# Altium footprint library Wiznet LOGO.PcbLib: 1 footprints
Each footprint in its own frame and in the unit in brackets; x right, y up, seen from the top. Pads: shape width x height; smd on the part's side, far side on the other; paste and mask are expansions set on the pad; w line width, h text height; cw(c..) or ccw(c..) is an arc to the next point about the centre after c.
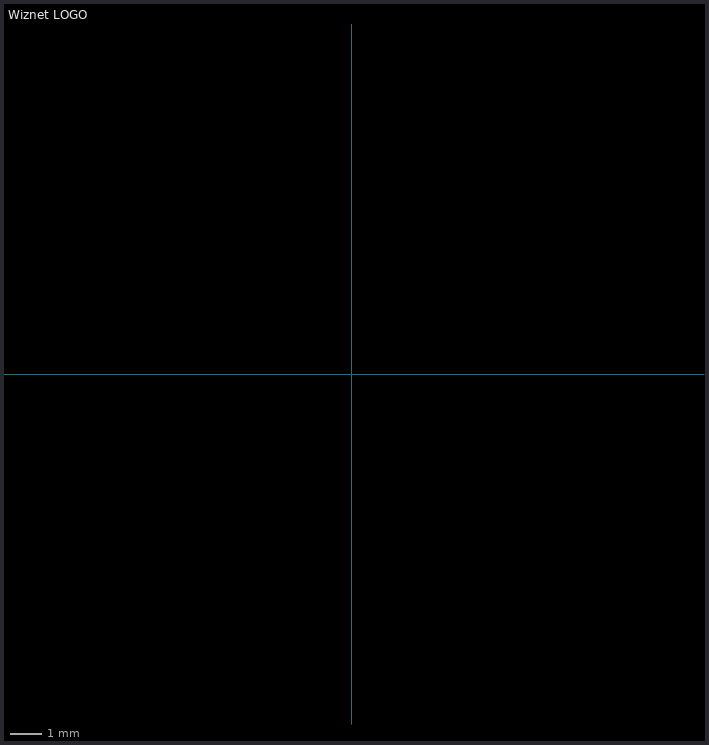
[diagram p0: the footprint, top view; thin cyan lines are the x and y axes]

## Wiznet LOGO [mm] "Wiznet LOGO"
Bottom Overlay:
  drawing of 797 lines, arcs and shapes, not listed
